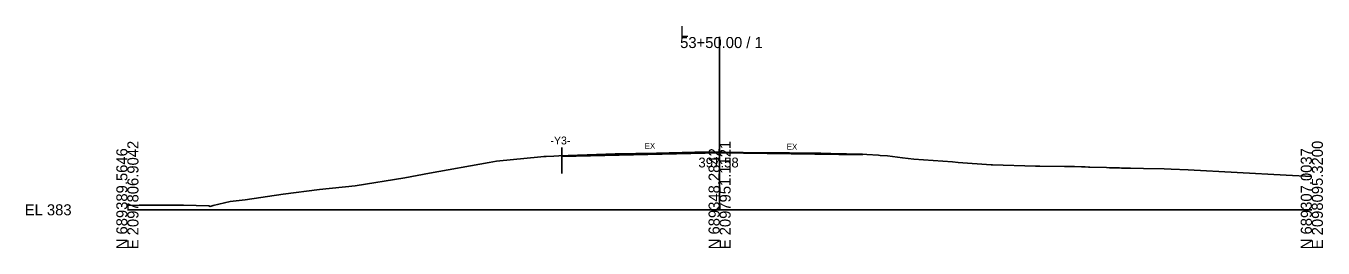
# Model space of a CAD drawing. Extents: x -26 to 8203, y -10 to 9546.
# Drawn here: x 6574.3 to 6902.8, y -9.7 to 46.6 of the extents above; entities that cross this region are included whole.
import ezdxf

# ---------------------------------------------------------------- set-up
doc = ezdxf.new("R2010")
doc.units = 0
for name, color, linetype in [('Default', 7, 'Continuous'), ('Exist CMT Pavement', 7, 'Continuous'), ('Exist Cross Section Cell', 7, 'Continuous'), ('Exist XS Ground Line', 7, 'Continuous'), ('Prop CMT Pvmt Course 1 Wedge', 7, 'Continuous'), ('Prop CMT Pvmt Course 3 Wedge', 7, 'Continuous'), ('Prop CMT Shear Line', 7, 'Continuous'), ('Prop CMT Shear Line Text', 7, 'Continuous'), ('Prop XS SE Text', 7, 'Continuous')]:
    doc.layers.add(name, color=color, linetype=linetype)

msp = doc.modelspace()

# ---------------------------------------------------------------- linework, layer by layer
at = {"layer": 'Exist CMT Pavement'}
msp.add_lwpolyline([(6600, 1.12), (6603, 1.15), (6603.71, 1.16), (6604.03, 1.15), (6604.57, 1.15), (6614.24, 1.14), (6620.6, 0.98), (6621, 0.87), (6621.72, 1.11), (6626.05, 2.1), (6629.79, 2.49), (6639.48, 3.94), (6648.68, 5.11), (6657.67, 6.07), (6670.31, 8.12), (6676.56, 9.32), (6691.61, 11.99), (6693.46, 12.32), (6704.74, 13.43), (6705.44, 13.51), (6706.07, 13.54), (6707.99, 13.59), (6709.31, 13.64), (6723.53, 14.15), (6734.05, 14.36), (6743.76, 14.57), (6746.2, 14.57), (6748.8, 14.59), (6749.35, 14.59), (6750, 14.58), (6750.58, 14.58), (6753.49, 14.51), (6767.66, 14.42), (6775.67, 14.35), (6778.15, 14.27), (6786.2, 14.06), (6787.28, 14), (6790.23, 13.87), (6790.65, 13.78), (6792.54, 13.68), (6796.28, 13.16), (6799.2, 12.83), (6808.96, 12.12), (6810.38, 11.99), (6818.76, 11.42), (6819.08, 11.4), (6830.02, 11.09), (6831.13, 11.07), (6837.32, 10.96), (6838.2, 10.94), (6839.89, 10.94), (6841.62, 10.92), (6842.59, 10.89), (6843.41, 10.84), (6843.75, 10.83), (6847.99, 10.69), (6848.73, 10.67), (6849.38, 10.66), (6850.18, 10.63), (6850.77, 10.61), (6851.3, 10.6), (6851.78, 10.59), (6852.44, 10.58), (6853.01, 10.57), (6853.53, 10.56), (6854.03, 10.55), (6857.32, 10.47), (6862.56, 10.39), (6864.4, 10.33), (6868.67, 10.12), (6893.47, 8.78), (6900, 8.42)], dxfattribs=at)
at = {"layer": 'Exist Cross Section Cell'}
for p, q in [((6750, 0), (6750, 43.78)), ((6600, 0), (6750, 0)), ((6750, 0), (6900, 0))]:
    msp.add_line(p, q, dxfattribs=at)
at = {"layer": 'Prop CMT Pvmt Course 1 Wedge'}
for q in [(6710, 13.54), (6786.19, 13.93)]:
    msp.add_line((6750, 14.46), q, dxfattribs=at)
at = {"layer": 'Prop CMT Pvmt Course 3 Wedge'}
for p, q in [((6750, 14.58), (6710, 13.66)), ((6710, 13.66), (6710, 13.54)), ((6750, 14.58), (6786.19, 14.06)), ((6786.19, 14.06), (6786.19, 13.93))]:
    msp.add_line(p, q, dxfattribs=at)
at = {"layer": 'Prop CMT Shear Line'}
msp.add_line((6710, 15.76), (6710, 9.19), dxfattribs=at)

# ---------------------------------------------------------------- texts
at = {"layer": 'Default'}
msp.add_text('-', height=0.0001, dxfattribs=at).set_placement((6600, 0))
at = {"layer": 'Exist Cross Section Cell'}
for s, p in [('L', (6740, 43.78)), ('53+50.00 / 1', (6740, 40.98)), ('EL 383', (6574, -1.4))]:
    msp.add_text(s, height=2.8, dxfattribs=at).set_placement(p)
for s, p in [('E 2097806.9042', (6602.8, -10)), ('E 2097951.1121', (6752.8, -10)), ('E 2098095.3200', (6902.8, -10)), ('N 689389.5646', (6600, -10)), ('N 689348.2842', (6750, -10)), ('N 689307.0037', (6900, -10))]:
    msp.add_text(s, height=2.8, rotation=90, dxfattribs=at).set_placement(p)
at = {"layer": 'Exist XS Ground Line'}
msp.add_text('397.58', height=2.5, dxfattribs=at).set_placement((6744.62, 10.73))
at = {"layer": 'Prop CMT Shear Line Text'}
msp.add_text('-Y3-', height=2, dxfattribs=at).set_placement((6707.15, 16.56))
at = {"layer": 'Prop XS SE Text'}
for rotation, p in [(1.1458, (6731.03, 15.41)), (358.9331, (6766.98, 15.26))]:
    msp.add_text('EX', height=1.5, rotation=rotation, dxfattribs=at).set_placement(p)

doc.saveas('drawing.dxf')
